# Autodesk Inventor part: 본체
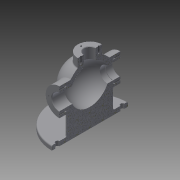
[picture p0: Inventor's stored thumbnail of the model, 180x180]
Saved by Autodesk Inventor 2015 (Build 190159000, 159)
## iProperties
Created: 2020-08
Part Number: 본체
Material: 일반
Document SubType Name: Modeling
Designer: 101548
Density: 1 g/cm^3
Appearance: 기본값
Author: 101548
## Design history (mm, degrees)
sketch "스케치1"
  geometry: L1 (53, 0)-(-53, 0); A1 r 53 centre (0, 0) between (53, 0) and (-53, 0); 2 further points
  constraints: 2 end point, 2 point on circle, 1 centre point, 1 coincident, 1 horizontal, 1 midpoint
  dimensions: "d0" = 106 distance of L1.start L1.end; "d1" = 53 radius of A1
revolve "회전1" sketch "스케치1" stored, may be unused: angle "d2" = 90 deg
sketch "스케치2"
  geometry: L1 (43, 0)-(-43, 0); A1 r 43 centre (0, 0) between (43, 0) and (-43, 0); 2 further points
  constraints: 2 end point, 2 point on circle, 1 centre point, 1 coincident, 1 horizontal, 1 midpoint
  dimensions: "d3" = 86 distance of L1.start L1.end; "d4" = 43 radius of A1
revolve "회전2" sketch "스케치2" stored, may be unused: angle "d5" = 90 deg
node "작업 평면1"
sketch "스케치3"
  geometry: C1 r 85 at (0, 0); 1 further point
  constraints: 1 centre point, 1 coincident
  dimensions: "d7" = 170 diameter of C1
extrude "돌출1" join sketch "스케치3" distance "d8" = 10; taper "d9" = 0 deg
sketch "스케치4"
  geometry: C1 r 85 at (0, 0) reference; 1 further point
  constraints: 1 vertical alignment
  dimensions: "d10" = 72.5 distance of C1.centre point (0, -72.5)
hole "구멍1" sketch "스케치4" at (0, -72.5) diameter "d11" = 9; stored, may be unused: countersink angle "d15" = 90 deg, drill point angle "d17" = 118 deg; dims "d12" = 6, "d13" = 4, "d14" = 2, "d16" = 8
sketch "스케치5"
  geometry: L1 (4, -52)-(-4, -52); L2 (-4, -52)-(-4, 52); L3 (-4, 52)-(4, 52); L4 (4, 52)-(4, -52); L5 (4, -52)-(-4, 52); L6 (-4, -52)-(4, 52); L7 (-43, -4)-(43, -4); L8 (43, -4)-(43, 4); L9 (43, 4)-(-43, 4); L10 (-43, 4)-(-43, -4); L11 (-43, -4)-(43, 4); L12 (43, -4)-(-43, 4); C1 r 85 at (0, 0) reference
  constraints: 24 end point, 4 midpoint, 4 parallel, 2 horizontal, 2 perpendicular
  dimensions: "d21" = 8 distance of L2.end L3.end; "d22" = 8 distance of L9.end L7.start; "d23" = 86 distance of L8.end L9.end; "d24" = 104 distance of L3.end L1.start
extrude "돌출2" join sketch "스케치5" stored distance "d25" = 75; taper "d26" = 0 deg
node "작업 평면2"
sketch "스케치6"
  geometry: C1 r 31 at (0, 0); 1 further point
  constraints: 1 centre point, 1 coincident
  dimensions: "d28" = 62 diameter of C1
extrude "돌출3" join sketch "스케치6" stored distance "d29" = 75; taper "d30" = 0 deg
sketch "스케치7"
  geometry: C1 r 31 at (0, 0) reference; C2 r 17.5 at (0, 0)
  constraints: 1 centre point, 1 coincident
  dimensions: "d31" = 35 diameter of C2
extrude "돌출4" cut sketch "스케치7" stored distance "d32" = 16; taper "d33" = 0 deg
node "작업 평면4"
sketch "스케치9"
  geometry: C1 r 27 at (0, 0); 1 further point
  constraints: 1 centre point, 1 coincident
  dimensions: "d39" = 54 diameter of C1
extrude "돌출6" join sketch "스케치9" stored distance "d40" = 1.75; taper "d41" = 0 deg
sketch "스케치10"
  geometry: C1 r 27 at (0, 0) reference; C2 r 13 at (0, 0)
  constraints: 1 centre point, 1 coincident
  dimensions: "d42" = 26 diameter of C2
extrude "돌출7" cut sketch "스케치10" stored distance "d43" = 1.75; taper "d44" = 0 deg
sketch "스케치11"
  geometry: C1 r 17.5 at (0, 0) reference; 1 further point
  constraints: 1 vertical alignment
  dimensions: "d45" = 24 distance of C1.centre point (0, 24)
hole "구멍2" sketch "스케치11" at (0, 24) diameter "d46" = 3.242; stored, may be unused: countersink angle "d50" = 90 deg, drill point angle "d52" = 118 deg; dims "d47" = 12, "d48" = 4, "d49" = 2, "d51" = 15
sketch "스케치12"
  geometry: C1 r 17.5 at (0, 0) reference; 1 further point
  constraints: 1 vertical alignment
  dimensions: "d56" = 24 distance of C1.centre point (0, -24)
hole "구멍3" sketch "스케치12" at (0, -24) diameter "d57" = 3.242; stored, may be unused: countersink angle "d61" = 90 deg, drill point angle "d63" = 118 deg; dims "d58" = 12, "d59" = 4, "d60" = 2, "d62" = 15
sketch "스케치13"
  geometry: C1 r 13 at (0, 0) reference; 1 further point
  constraints: 1 vertical alignment
  dimensions: "d67" = 20 distance of C1.centre point (0, 20)
hole "구멍4" sketch "스케치13" at (0, 20) diameter "d68" = 3.242; stored, may be unused: countersink angle "d72" = 90 deg, drill point angle "d74" = 118 deg; dims "d69" = 12, "d70" = 4, "d71" = 2, "d73" = 15
chamfer "모따기1" distance "d78" = 1; stored, may be unused: second distance "d79" = 2, angle "d80" = 45 deg
fillet "모깎기1" dims "d81" = 3
fillet "모깎기2" dims "d82" = 3
fillet "모깎기3" dims "d83" = 3
fillet "모깎기4" dims "d84" = 3
fillet "모깎기5" dims "d85" = 3
node "작업 평면5"
sketch "스케치14"
  geometry: L1 (27, 0)-(-27, 0) reference; 2 further points
  constraints: 1 other
  dimensions: "d86" = 9 distance from line of L1 point (0, -9); "d87" = 27 horizontal distance of L1.end point (0, -9)
feature "엠보싱1" sketch "스케치14" dims "d10" = 72.5, "d88" = 0.5, "d89" = 0
node "작업 평면6"
sketch "스케치15"
  geometry: C1 r 18.5 at (0, 0); 1 further point
  constraints: 1 centre point, 1 coincident
  dimensions: "d91" = 37 diameter of C1
extrude "돌출8" cut sketch "스케치15" distance "d92" = 1.75; taper "d93" = 0 deg
node "솔리드1"
pattern_circular "원형 패턴1" dims angle "d19" = 360 deg
mirror "대칭1"
pattern_circular "원형 패턴2" dims angle "d54" = 360 deg
pattern_circular "원형 패턴3" dims angle "d65" = 360 deg
pattern_circular "원형 패턴4" dims angle "d76" = 360 deg
other parameters: "d6" = -85, "d27" = -68, "d90" = -16
